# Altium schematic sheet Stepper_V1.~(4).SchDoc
size A4; SheetNumber: 4; SheetTotal: 5
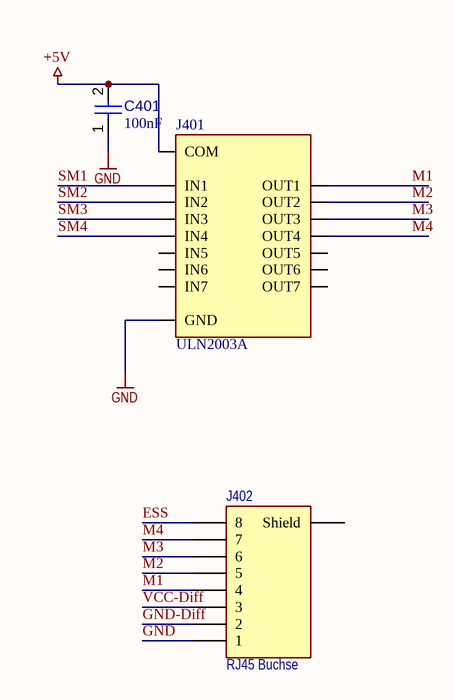
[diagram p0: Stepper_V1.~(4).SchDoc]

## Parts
C401  value 100nF  [CAPC1608X90X40NL10T20]  (hidden comment: Capacitor 100 nF +/-10% 50 V 0603)
J401  ULN2003A  [TSSOP-16-TI]
J402  RJ45 Buchse  [J_TE-RJ45-8L-B]

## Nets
+5V: C401.2 J401.9(COM)
GND: C401.1 J401.8(GND) J402.1
ESS: J402.8
GND-Diff: J402.2
M1: J401.16(OUT1) J402.4
M2: J401.15(OUT2) J402.5
M3: J401.14(OUT3) J402.6
M4: J401.13(OUT4) J402.7
SM1: J401.1(IN1)
SM2: J401.2(IN2)
SM3: J401.3(IN3)
SM4: J401.4(IN4)
VCC-Diff: J402.3

Not connected (* = marked no-connect by the designer): J401 5(IN5) 6(IN6) 7(IN7) 10(OUT7) 11(OUT6) 12(OUT5); J402 MP(Shield)

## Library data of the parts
C401 = CMP-001-00017-6: Chip Capacitor, 100 nF, +/- 10%, 50 V, 0603 (1608 Metric); Voltage Rating: 50V; Capacitor Type: Ceramic
J401 = ULN2003A: DARLINGTON ARRAY 7NPN, 2003, DIP16; Transistor Polarity:NPN; Collector Emitter Voltage V(br)ceo:50V; DC Collector Current:500mA; DC Current Gain hFE:1000; Operating Temperature Range:-20Â°C to +85Â°C; Transistor Case Style:DIP; No. of Pins:16; SVHC:No SVH; MF: STMicroelectronics
J402 = J_RJ45: Connector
